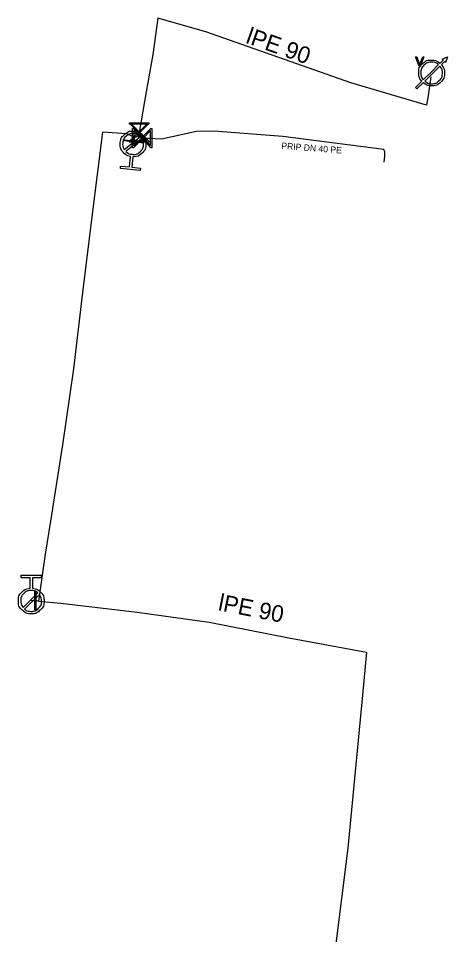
# Model space of a CAD drawing. Extents: x -643544 to -637295, y -1119190 to -1111715.
# Drawn here: x -642527.2 to -642493.7, y -1114138.1 to -1114066.6 of the extents above; entities that cross this region are included whole.
import ezdxf

# ---------------------------------------------------------------- set-up
doc = ezdxf.new("R2010")
doc.units = 0
for name, color, linetype in [('Default', 7, 'Continuous'), ('VP Hydrant', 7, 'Continuous'), ('VP Popis přípojky', 7, 'Continuous'), ('VP Přípojka', 7, 'Continuous'), ('VP Vodoměr', 7, 'Continuous'), ('VP Řad', 7, 'Continuous'), ('VP Řad - popis', 7, 'Continuous'), ('VP Šoupě', 7, 'Continuous')]:
    doc.layers.add(name, color=color, linetype=linetype)

msp = doc.modelspace()

# ---------------------------------------------------------------- linework, layer by layer
at = {"layer": 'Default'}
for points in [[(-642495.725, -1114071.554), (-642495.967, -1114071.277), (-642495.967, -1114070.9), (-642495.967, -1114070.483), (-642495.672, -1114070.188), (-642495.377, -1114069.893), (-642494.96, -1114069.893), (-642494.583, -1114069.893), (-642494.306, -1114070.135)], [(-642495.921, -1114070.17), (-642495.899, -1114070.232), (-642495.883, -1114070.287), (-642495.867, -1114070.229), (-642495.845, -1114070.17)], [(-642494.424, -1114070.253), (-642494.652, -1114070.06), (-642494.96, -1114070.06), (-642495.308, -1114070.06), (-642495.553, -1114070.306), (-642495.799, -1114070.552), (-642495.799, -1114070.9), (-642495.799, -1114071.208), (-642495.607, -1114071.436)], [(-642494.195, -1114070.244), (-642493.953, -1114070.522), (-642493.953, -1114070.9), (-642493.953, -1114071.317), (-642494.248, -1114071.612), (-642494.543, -1114071.907), (-642494.96, -1114071.907), (-642495.337, -1114071.907), (-642495.616, -1114071.665)], [(-642495.496, -1114071.546), (-642495.268, -1114071.739), (-642494.96, -1114071.739), (-642494.612, -1114071.739), (-642494.366, -1114071.493), (-642494.12, -1114071.248), (-642494.12, -1114070.9), (-642494.12, -1114070.591), (-642494.313, -1114070.364)], [(-642518.418, -1114077.421), (-642518.772, -1114077.353), (-642519.001, -1114077.067), (-642519.259, -1114076.745), (-642519.214, -1114076.331), (-642519.17, -1114075.919), (-642518.847, -1114075.66), (-642518.525, -1114075.401), (-642518.111, -1114075.446), (-642517.701, -1114075.49), (-642517.441, -1114075.812), (-642517.181, -1114076.133), (-642517.226, -1114076.545), (-642517.27, -1114076.959), (-642517.591, -1114077.219), (-642517.875, -1114077.451), (-642518.235, -1114077.44)], [(-642517.647, -1114075.861), (-642517.844, -1114075.665), (-642518.131, -1114075.634), (-642518.465, -1114075.598), (-642518.728, -1114075.809), (-642518.99, -1114076.019), (-642519.026, -1114076.355), (-642519.057, -1114076.643), (-642518.907, -1114076.877)], [(-642518.793, -1114077.019), (-642518.596, -1114077.219), (-642518.305, -1114077.25), (-642517.969, -1114077.286), (-642517.708, -1114077.076), (-642517.447, -1114076.865), (-642517.41, -1114076.529), (-642517.379, -1114076.238), (-642517.533, -1114076.003)], [(-642526.067, -1114111.09), (-642525.708, -1114111.119), (-642525.45, -1114111.379), (-642525.159, -1114111.672), (-642525.159, -1114112.088), (-642525.159, -1114112.502), (-642525.452, -1114112.794), (-642525.745, -1114113.086), (-642526.161, -1114113.086), (-642526.573, -1114113.086), (-642526.866, -1114112.794), (-642527.159, -1114112.502), (-642527.159, -1114112.088), (-642527.159, -1114111.672), (-642526.868, -1114111.379), (-642526.61, -1114111.117), (-642526.251, -1114111.09)], [(-642525.651, -1114111.449), (-642525.868, -1114111.272), (-642526.161, -1114111.272), (-642526.499, -1114111.272), (-642526.736, -1114111.509), (-642526.973, -1114111.746), (-642526.973, -1114112.084), (-642526.973, -1114112.377), (-642526.796, -1114112.594)], [(-642526.667, -1114112.723), (-642526.45, -1114112.897), (-642526.161, -1114112.897), (-642525.825, -1114112.897), (-642525.587, -1114112.659), (-642525.348, -1114112.422), (-642525.348, -1114112.084), (-642525.348, -1114111.795), (-642525.522, -1114111.578)]]:
    msp.add_open_spline(points, degree=3, dxfattribs=at)
at = {"layer": 'VP Hydrant'}
for points in [[(-642518.907, -1114076.877), (-642517.647, -1114075.861)], [(-642517.533, -1114076.003), (-642518.793, -1114077.019)], [(-642518.235, -1114077.44), (-642518.323, -1114078.256), (-642517.637, -1114078.33), (-642517.657, -1114078.512), (-642519.211, -1114078.345), (-642519.191, -1114078.162), (-642518.506, -1114078.236), (-642518.418, -1114077.421)], [(-642526.251, -1114111.09), (-642526.251, -1114110.27), (-642526.94, -1114110.27), (-642526.94, -1114110.086), (-642525.378, -1114110.086), (-642525.378, -1114110.27), (-642526.067, -1114110.27), (-642526.067, -1114111.09)], [(-642526.796, -1114112.594), (-642525.651, -1114111.449)], [(-642525.522, -1114111.578), (-642526.667, -1114112.723)]]:
    msp.add_lwpolyline(points, dxfattribs=at)
at = {"layer": 'VP Přípojka'}
for points in [[(-642498.658, -1114077.864), (-642498.61, -1114077.38), (-642498.61, -1114077.06), (-642498.69, -1114076.87), (-642506.54, -1114075.86), (-642511.94, -1114075.44), (-642513.29, -1114075.48), (-642516.01, -1114076.06), (-642517.51, -1114075.98), (-642517.82, -1114075.9)], [(-642518.1, -1114075.87), (-642518.15, -1114076.24), (-642518.22, -1114076.44)], [(-642525.6, -1114112.1), (-642525.84, -1114112.04), (-642526.159, -1114112.086)]]:
    msp.add_lwpolyline(points, dxfattribs=at)
at = {"layer": 'VP Vodoměr'}
for points in [[(-642495.932, -1114070.365), (-642496.21, -1114069.65), (-642496.107, -1114069.65), (-642495.921, -1114070.17)], [(-642495.845, -1114070.17), (-642495.651, -1114069.65), (-642495.554, -1114069.65), (-642495.835, -1114070.365), (-642495.932, -1114070.365)], [(-642494.065, -1114069.894), (-642494.14, -1114069.821), (-642493.71, -1114069.65), (-642493.88, -1114070.08), (-642493.955, -1114070.005), (-642494.195, -1114070.244)], [(-642495.607, -1114071.436), (-642495.002, -1114070.83), (-642494.424, -1114070.253)], [(-642494.313, -1114070.364), (-642495.155, -1114071.206), (-642495.496, -1114071.546)], [(-642494.306, -1114070.135), (-642494.065, -1114069.894)], [(-642495.616, -1114071.665), (-642496.099, -1114072.15), (-642496.21, -1114072.039), (-642495.725, -1114071.554)]]:
    msp.add_lwpolyline(points, dxfattribs=at)
at = {"layer": 'VP Řad'}
msp.add_lwpolyline([(-642495.03, -1114071.2), (-642495.26, -1114072.83), (-642495.32, -1114073.26), (-642495.35, -1114073.41), (-642501.26, -1114071.68), (-642512.56, -1114067.7), (-642516.29, -1114066.64), (-642516.69, -1114069.46), (-642517.199, -1114072.382), (-642517.75, -1114075.55), (-642517.82, -1114075.9), (-642518.32, -1114075.83), (-642518.7, -1114075.65), (-642520.6, -1114075.52), (-642521.43, -1114082.13), (-642522.17, -1114088.02), (-642522.86, -1114093.98), (-642523.72, -1114099.9), (-642524.65, -1114105.86), (-642525.08, -1114108.43), (-642525.6, -1114112.1), (-642523.84, -1114112.25), (-642517.9, -1114112.97), (-642512.28, -1114113.73), (-642506.09, -1114114.96), (-642500.03, -1114116.09), (-642500.337, -1114119.428), (-642500.92, -1114125.4), (-642501.5, -1114131.38), (-642502.97, -1114143.14)], dxfattribs=at)
at = {"layer": 'VP Šoupě'}
for points in [[(-642518.5, -1114074.8), (-642517, -1114074.8), (-642517, -1114074.866), (-642517.094, -1114074.954), (-642517.687, -1114075.549), (-642517, -1114076.234), (-642517, -1114076.3), (-642518.5, -1114076.3), (-642518.5, -1114076.234), (-642517.812, -1114075.549), (-642518.406, -1114074.955), (-642518.5, -1114074.866), (-642518.5, -1114074.8)], [(-642518.343, -1114074.894), (-642517.749, -1114075.486), (-642517.158, -1114074.894), (-642518.343, -1114074.894)], [(-642516.76, -1114075.23), (-642516.76, -1114076.73), (-642516.826, -1114076.73), (-642516.914, -1114076.636), (-642517.509, -1114076.043), (-642518.194, -1114076.73), (-642518.26, -1114076.73), (-642518.26, -1114075.23), (-642518.194, -1114075.23), (-642517.509, -1114075.918), (-642516.915, -1114075.324), (-642516.826, -1114075.23), (-642516.76, -1114075.23)], [(-642518.166, -1114076.578), (-642517.571, -1114075.981), (-642518.166, -1114075.387), (-642518.166, -1114076.578)], [(-642516.854, -1114075.387), (-642517.446, -1114075.981), (-642516.854, -1114076.572), (-642516.854, -1114075.387)], [(-642518.89, -1114076.107), (-642517.4, -1114076.28), (-642517.41, -1114076.373), (-642518.9, -1114076.2), (-642518.89, -1114076.107)], [(-642517.152, -1114076.206), (-642517.749, -1114075.611), (-642518.343, -1114076.206), (-642517.152, -1114076.206)], [(-642525.793, -1114111.29), (-642525.793, -1114112.79), (-642525.887, -1114112.79), (-642525.887, -1114111.29), (-642525.793, -1114111.29)]]:
    msp.add_lwpolyline(points, dxfattribs=at)

# ---------------------------------------------------------------- texts
at = {"layer": 'VP Popis přípojky'}
msp.add_text('PRIP DN 40 PE', height=0.5, rotation=355.55262, dxfattribs=at).set_placement((-642506.681, -1114076.821))
at = {"layer": 'VP Řad - popis'}
for rotation, p in [(340.5971, (-642509.51, -1114068.541)), (348.76129, (-642511.646, -1114112.795))]:
    msp.add_text('lPE 90', height=1.3, rotation=rotation, dxfattribs=at).set_placement(p)

doc.saveas('drawing.dxf')
